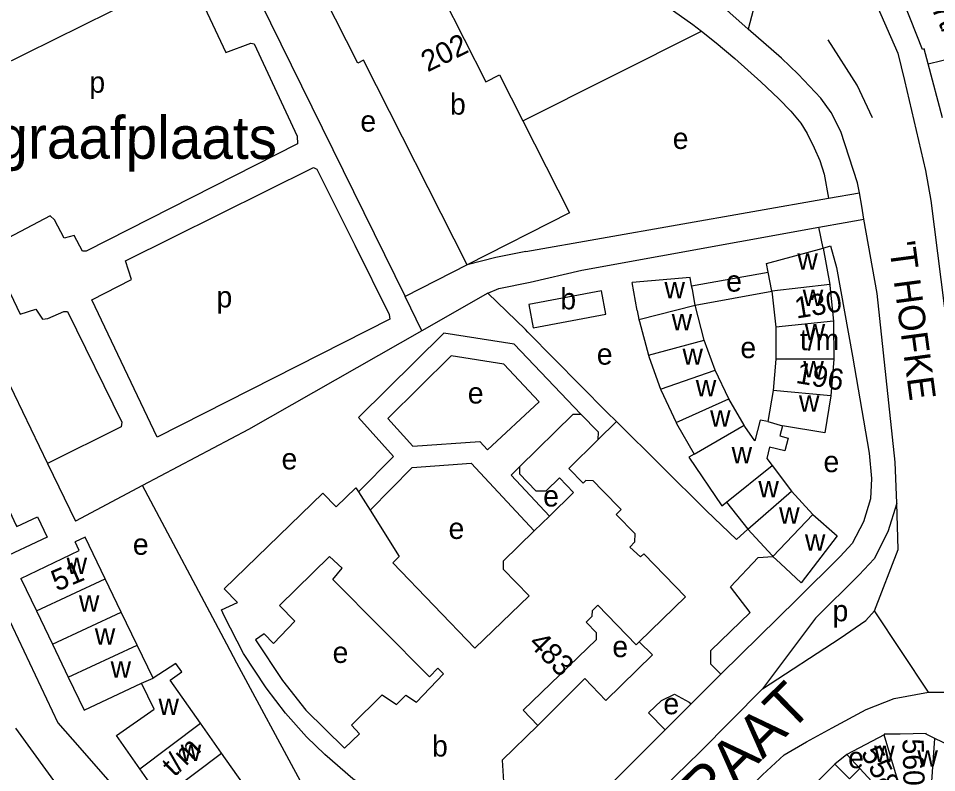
# Model space of a CAD drawing. Extents: x 162883 to 165538, y 383986 to 385172.
# Drawn here: x 163911.8 to 164085, y 384315.2 to 384457.6 of the extents above; entities that cross this region are included whole.
import ezdxf

# ---------------------------------------------------------------- set-up
doc = ezdxf.new("R2010")
doc.units = 0
for name, color, linetype in [('BLT_Basislijn', 7, 'Continuous'), ('BLT_Bebouwing', 7, 'Continuous'), ('BLT_Centroide', 7, 'Continuous'), ('BLT_Huisnummer', 7, 'Continuous'), ('BLT_Huisnummer_reeks', 7, 'Continuous'), ('BLT_Onderverdeling_panden', 7, 'Continuous'), ('BLT_Straatnaam', 7, 'Continuous'), ('BLT_Straatnaam_hoofdweg', 7, 'Continuous'), ('BLT_Terrein_beschrifting', 7, 'Continuous'), ('BLT_Vlakafsluiter', 7, 'Continuous')]:
    doc.layers.add(name, color=color, linetype=linetype)

msp = doc.modelspace()

# ---------------------------------------------------------------- linework, layer by layer
at = {"layer": 'BLT_Basislijn'}
for p, q in [((163886.33, 384437.63), (163943.9, 384466.17)), ((164006.95, 384438.24), (164040.63, 384455.16)), ((163886.33, 384437.63), (163917.29, 384373.57)), ((164063.81, 384428.18), (164064.64, 384423.62)), ((164007.5, 384413.59), (164064.64, 384423.62)), ((164064.64, 384423.62), (164070.44, 384424.64)), ((164063.59, 384414.21), (164062.79, 384418.14)), ((164067.77, 384419.04), (164071.31, 384419.66)), ((164038.8, 384407.07), (164053.23, 384409.69)), ((164039.45, 384403.47), (164053.95, 384406.1)), ((163987.9, 384398.58), (163984.73, 384405.1)), ((164000.34, 384405.72), (163987.9, 384398.58)), ((164007.43, 384398.86), (164000.34, 384405.72)), ((164010.06, 384385.2), (164000.31, 384376.13)), ((164021.13, 384378.04), (164024.6, 384381.5)), ((163975.93, 384368.19), (163982.54, 384374.91)), ((163917.29, 384373.57), (163922.54, 384362.69)), ((163978.13, 384364.73), (163986.08, 384372.81)), ((163935.22, 384369.4), (163922.54, 384362.69)), ((164058.65, 384347.89), (164044.46, 384333.93)), ((164044.46, 384333.93), (164038.7, 384328.19)), ((164038.7, 384328.19), (164033.81, 384323.31)), ((163924.02, 384306.15), (163911.31, 384323.59)), ((164033.81, 384323.31), (164013.39, 384302.89)), ((164068.09, 384318.64), (164065.79, 384316.81))]:
    msp.add_line(p, q, dxfattribs=at)
for points in [[(163952.32, 384470.24), (163955.43, 384464.7), (163984.73, 384405.1)], [(164049.47, 384455.56), (164039.63, 384464.36), (164031.94, 384470.28)], [(164025.61, 384468.33), (164028.5, 384463.91), (164039.03, 384456.44), (164040.63, 384455.16)], [(163943.9, 384466.17), (163950.95, 384451.13), (163955.61, 384452.91), (163956.25, 384452.75), (163964.39, 384435.33), (163964.46, 384433.9), (163924.56, 384413.66), (163923.89, 384413.66), (163922.33, 384416.58), (163920.39, 384416.11), (163918.58, 384419.58), (163917.78, 384420.28), (163906.37, 384414.35), (163907.09, 384412.19), (163912.15, 384401.77), (163915.08, 384402.72), (163916.35, 384400.81), (163917.32, 384400.94), (163920.33, 384402.27), (163921.06, 384402.24), (163931.28, 384381.36), (163931.15, 384380.49), (163917.29, 384373.57)], [(164073.79, 384459.86), (164077.68, 384451.03), (164078.94, 384445.85), (164082.94, 384428.86), (164083.91, 384423.22), (164088.33, 384388.44), (164089.21, 384364.99), (164089.69, 384360.4), (164090.61, 384357.27), (164091.09, 384356.07), (164094.4, 384348.23), (164098.89, 384337.66)], [(164040.63, 384455.16), (164043.44, 384452.94), (164046.96, 384450.01), (164051.83, 384445.61), (164055.24, 384442.39), (164057.52, 384440.07), (164059.37, 384437.82), (164060.6, 384435.83), (164061.92, 384433.16), (164062.96, 384430.78), (164063.81, 384428.18)], [(164070.44, 384424.64), (164070.11, 384426.53), (164066.97, 384436.23), (164065.11, 384439.84), (164063.17, 384442.49), (164058.89, 384447.05), (164055.76, 384450.09), (164049.47, 384455.56)], [(164072.92, 384438.82), (164070.02, 384444.95), (164064.55, 384453.5)], [(163975.24, 384414.76), (163981.73, 384401.7), (163981.87, 384400.78), (163937.99, 384378.54), (163925.61, 384404.46), (163933.1, 384408.32), (163932, 384411.79), (163967.45, 384429.41), (163968.08, 384429.1), (163975.24, 384414.76)], [(164070.88, 384422.15), (164070.44, 384424.64)], [(164000.34, 384405.72), (164002.41, 384406.62), (164008.36, 384407.8), (164018.1, 384410.06), (164062.79, 384418.14)], [(164062.79, 384418.14), (164067.77, 384419.04)], [(164077.48, 384366.07), (164077.2, 384373.82), (164073.78, 384405.64), (164071.31, 384419.66)], [(164063.59, 384414.21), (164064.98, 384414.66), (164066.1, 384410.58), (164069.15, 384393.83), (164072.28, 384375.52), (164072.7, 384370.74), (164072.51, 384366.92), (164071.19, 384362.53), (164069.08, 384358.46), (164066.83, 384356.04), (164058.65, 384347.89)], [(164007.5, 384413.59), (164001.84, 384412.47), (163996.47, 384411.07)], [(163996.47, 384411.07), (163984.73, 384405.1)], [(163987.9, 384398.58), (163955.2, 384379.98), (163935.22, 384369.4)], [(164017.89, 384382.87), (164005.31, 384396.07), (163992.04, 384398.14), (163975.97, 384382.23), (163982.54, 384374.91)], [(164024.6, 384381.5), (164022.82, 384383.27), (164007.92, 384398.37), (164007.43, 384398.86)], [(164010.06, 384385.2), (164003.34, 384392.33), (163993.42, 384393.87), (163981.49, 384382.07), (163986.19, 384376.83), (163998.81, 384377.73), (164000.31, 384376.13)], [(164049.39, 384361.14), (164047.29, 384359.24), (164041.59, 384364.6), (164024.6, 384381.5)], [(163986.08, 384372.81), (163997.19, 384373.61), (164009.09, 384360.84)], [(164006.32, 384372.96), (164004.73, 384371.39), (164011.96, 384363.64)], [(163953.02, 384335.9), (163951.11, 384339.44), (163935.22, 384369.4)], [(164077.48, 384366.07), (164075.84, 384360.64), (164073.21, 384355.55), (164070.42, 384352.56), (164062.18, 384344.35), (164052.17, 384331.03)], [(164073.3, 384345.74), (164077.79, 384357.34), (164077.48, 384366.07)], [(164044.24, 384333.88), (164042.44, 384335.66), (164042.39, 384338.27), (164049.82, 384345.45), (164046.13, 384350.3), (164051.37, 384355.84), (164054.11, 384356.04)], [(163907.39, 384349.55), (163919.21, 384324.59), (163921.98, 384321.44)], [(164052.17, 384331.03), (164066.83, 384340.61), (164071.69, 384343.92), (164073.3, 384345.74)], [(164028.92, 384339.93), (164031.4, 384337.42), (164022.62, 384328.85), (164018.64, 384333.01), (164009.77, 384324.1)], [(163994.61, 384284.11), (163966.15, 384312.12), (163965.02, 384313.63), (163953.02, 384335.9)], [(163964.42, 384228.4), (163986.24, 384250), (164052.16, 384314.79), (164056.26, 384318.57), (164060.48, 384321.02), (164065.34, 384323.67), (164071.72, 384327.14), (164076.99, 384329.2), (164083.5, 384330.4)], [(163996.88, 384276.8), (164040.36, 384319.07), (164052.17, 384331.03)], [(164033.81, 384323.31), (164030.64, 384326.48), (164033.12, 384328.86), (164035.59, 384330.04), (164038.35, 384328.5), (164038.7, 384328.19)], [(164083.5, 384330.4), (164088.02, 384330.42), (164090.13, 384329.25)], [(163921.98, 384321.44), (163926.89, 384315.85)], [(163926.89, 384315.85), (163930.34, 384311.93), (163974.78, 384266.34)]]:
    msp.add_lwpolyline(points, dxfattribs=at)
msp.add_lwpolyline([(163970.46, 384356.04), (163961.03, 384346.79), (163963.94, 384343.78), (163959.92, 384339.59), (163958.14, 384341.42), (163956.54, 384340.3), (163961.64, 384332.58), (163966, 384326.98), (163973.32, 384319.81), (163976.15, 384322.56), (163974.61, 384324.2), (163980.4, 384329.9), (163983.12, 384328.1), (163984.88, 384329.82), (163986.88, 384328.51), (163992.01, 384333.88), (163990.93, 384334.91), (163989.33, 384333.27), (163971.13, 384351.65), (163972.88, 384353.81)], close=True, dxfattribs=at)
at = {"layer": 'BLT_Bebouwing'}
for p, q in [((164086.13, 384438.81), (164083.42, 384448.97)), ((164063.59, 384414.21), (164064.86, 384407.33)), ((164053.95, 384406.1), (164053.23, 384409.69)), ((164028.54, 384402.47), (164027.58, 384407.71)), ((164038.93, 384406.38), (164038.8, 384407.07)), ((164039.45, 384403.47), (164038.93, 384406.38)), ((164053.95, 384406.1), (164054.67, 384399.27)), ((164028.54, 384402.47), (164028.86, 384400.74)), ((164041.18, 384396.82), (164039.45, 384403.47)), ((164054.67, 384399.27), (164054.69, 384393.25)), ((164043.25, 384391.19), (164041.18, 384396.82)), ((164054.69, 384393.25), (164054.18, 384387.35)), ((164065.63, 384393.28), (164065.07, 384386.31)), ((164045.81, 384385.77), (164043.25, 384391.19)), ((164054.18, 384387.35), (164053.2, 384381.46)), ((164048.71, 384380.78), (164045.81, 384385.77)), ((164052.97, 384374.53), (164053.96, 384373.21)), ((164053.96, 384373.21), (164057.61, 384368.32)), ((163975.46, 384368.94), (163975.93, 384368.19)), ((163975.93, 384368.19), (163978.13, 384364.73)), ((164057.61, 384368.32), (164061.69, 384363.91)), ((164045.36, 384366.27), (164049.39, 384361.14)), ((164011.96, 384363.64), (164009.09, 384360.84)), ((164075.09, 384322.34), (164068.09, 384318.64)), ((164090.11, 384319.01), (164084.65, 384321.68)), ((164003.04, 384317.58), (164003.33, 384313.56)), ((164065.79, 384316.81), (164061.48, 384312.49))]:
    msp.add_line(p, q, dxfattribs=at)
for points in [[(163985.08, 384481.37), (163994.35, 384463.08), (163991.78, 384461.77), (163999.96, 384445.61), (164002.53, 384446.95), (164006.95, 384438.24)], [(164083.42, 384448.97), (164082.65, 384451.82), (164082.35, 384451.7), (164077.72, 384463.52), (164084.2, 384468.61), (164083.4, 384470.22), (164095.51, 384476.23)], [(163996.47, 384411.07), (163976.92, 384449.67), (163975.84, 384449.13), (163963.12, 384474.23)], [(164006.95, 384438.24), (164015.76, 384420.85), (163996.47, 384411.07)], [(164053.23, 384409.69), (164052.92, 384411.29), (164063.59, 384414.21)], [(164038.8, 384407.07), (164038.51, 384408.7), (164027.58, 384407.71)], [(164021.81, 384406.15), (164008.09, 384403.6), (164008.92, 384399.17)], [(164008.92, 384399.17), (164022.64, 384401.72), (164021.81, 384406.15)], [(164064.86, 384407.33), (164064.89, 384407.15), (164065.54, 384400.42)], [(164028.86, 384400.74), (164028.93, 384400.37), (164030.65, 384393.99)], [(164065.54, 384400.42), (164065.55, 384400.31), (164065.63, 384393.28)], [(164030.65, 384393.99), (164030.76, 384393.57), (164032.95, 384387.59)], [(164032.95, 384387.59), (164033, 384387.46), (164035.86, 384381.27)], [(164065.07, 384386.31), (164063.92, 384379.33), (164055.93, 384380.7)], [(164006.32, 384372.96), (164016.44, 384382.89), (164017.89, 384382.87)], [(164017.89, 384382.87), (164021.15, 384379.55), (164021.13, 384378.04)], [(164053.2, 384381.46), (164051.7, 384381.71), (164050.7, 384377.81)], [(164035.86, 384381.27), (164035.93, 384381.13), (164039.27, 384375.31)], [(164050.7, 384377.81), (164048.83, 384380.57), (164048.71, 384380.78)], [(164055.93, 384380.7), (164055.45, 384378.77), (164056.98, 384378.37), (164056.39, 384375.95), (164053.5, 384376.63), (164052.97, 384374.53)], [(164028.1, 384358.75), (164028.12, 384360.29), (164024.53, 384363.96), (164025.48, 384364.9), (164021.99, 384368.47), (164020.19, 384370.31), (164018.81, 384370.33), (164018.36, 384369.88), (164015.66, 384372.64), (164021.13, 384378.04)], [(164039.27, 384375.31), (164038.28, 384374.75), (164044.48, 384365.56), (164045.36, 384366.27)], [(164006.32, 384372.96), (164006.31, 384371.63), (164009.43, 384368.42), (164011.36, 384368.4), (164013.85, 384370.86), (164016.53, 384368.11), (164011.96, 384363.64)], [(163950.11, 384345.96), (163953.13, 384347.34), (163950.62, 384349.92), (163969.2, 384367.98), (163971.75, 384365.36), (163975.46, 384368.94)], [(163908.97, 384367.04), (163911.33, 384361.98), (163911.49, 384361.65), (163915.42, 384363.49), (163917.2, 384359.67), (163907.8, 384355.28)], [(163978.13, 384364.73), (163983.65, 384356.02), (163982.4, 384354.81), (163997.91, 384338.7)], [(164061.69, 384363.91), (164066.25, 384359.91), (164059.49, 384351.03), (164055.54, 384354.71), (164054.11, 384356.04)], [(164049.39, 384361.14), (164053.97, 384356.17), (164054.11, 384356.04)], [(163928.17, 384351.81), (163924.4, 384359.67), (163922.49, 384358.79)], [(164009.09, 384360.84), (164003.23, 384355.12), (164003.21, 384353.63), (164008.12, 384348.61), (163997.91, 384338.7)], [(163912.25, 384351.87), (163923.27, 384357.16), (163922.49, 384358.79)], [(164029.17, 384355.92), (164027.12, 384357.8), (164028.1, 384358.75)], [(164028.92, 384339.93), (164037.65, 384348.39), (164029.78, 384356.51)], [(164029.78, 384356.51), (164029.17, 384355.92)], [(163912.25, 384351.87), (163915.18, 384345.76)], [(163931.2, 384345.5), (163928.17, 384351.81)], [(163915.18, 384345.76), (163918.21, 384339.45)], [(163934.18, 384339.3), (163931.2, 384345.5)], [(163978.64, 384311.36), (163978.02, 384311.77), (163976.46, 384312.92), (163974.9, 384314.06), (163969.6, 384318.62), (163966.17, 384321.96), (163962.15, 384326.43), (163958.5, 384331.21), (163954.27, 384337.68), (163950.62, 384344.8), (163950.11, 384345.96)], [(164006.99, 384326.99), (164020.85, 384340.33), (164020.86, 384341.61), (164018.92, 384343.61), (164020.06, 384344.72), (164020.07, 384345.81), (164021.09, 384346.8), (164028.33, 384339.35), (164028.92, 384339.93)], [(163918.21, 384339.45), (163921.19, 384333.25)], [(163937.19, 384333.03), (163934.18, 384339.3)], [(163946.14, 384324.55), (163940.43, 384332.69), (163942.61, 384334.22), (163941.48, 384335.83), (163937.19, 384333.03)], [(163921.19, 384333.25), (163924.19, 384326.99), (163935.02, 384332.11)], [(163934.7, 384315.92), (163930.28, 384322.2), (163937.37, 384327.19), (163935.02, 384332.11)], [(164006.99, 384326.99), (164009.77, 384324.1)], [(163950.1, 384318.92), (163946.14, 384324.55)], [(164009.77, 384324.1), (164003.04, 384317.58)], [(164078.15, 384322.5), (164075.11, 384322.45), (164075.09, 384322.34)], [(164084.65, 384321.68), (164083.04, 384322.47), (164083.04, 384322.59), (164078.15, 384322.5)], [(163954.05, 384313.29), (163950.1, 384318.92)], [(164068.09, 384318.64), (164070.56, 384315.97)], [(163938.66, 384310.29), (163934.7, 384315.92)], [(164070.56, 384315.97), (164068.61, 384314.02), (164065.79, 384316.81)]]:
    msp.add_lwpolyline(points, dxfattribs=at)
at = {"layer": 'BLT_Onderverdeling_panden'}
for p, q in [((164064.86, 384407.33), (164053.95, 384406.1)), ((164028.86, 384400.74), (164039.45, 384403.47)), ((164065.54, 384400.42), (164054.67, 384399.27)), ((164030.65, 384393.99), (164041.18, 384396.82)), ((164065.63, 384393.28), (164054.69, 384393.25)), ((164032.95, 384387.59), (164043.25, 384391.19)), ((164065.07, 384386.31), (164054.18, 384387.35)), ((164035.86, 384381.27), (164045.81, 384385.77)), ((164039.27, 384375.31), (164048.71, 384380.78)), ((164053.2, 384381.46), (164055.93, 384380.7)), ((164045.36, 384366.27), (164053.96, 384373.21)), ((164049.39, 384361.14), (164057.61, 384368.32)), ((164054.11, 384356.04), (164061.69, 384363.91)), ((163915.18, 384345.76), (163928.17, 384351.81)), ((163918.21, 384339.45), (163931.2, 384345.5)), ((163921.19, 384333.25), (163934.18, 384339.3)), ((163935.02, 384332.11), (163937.19, 384333.03)), ((163934.7, 384315.92), (163946.14, 384324.55)), ((164077.81, 384313.28), (164075.09, 384322.34)), ((164083.96, 384311.76), (164084.65, 384321.68)), ((163938.66, 384310.29), (163950.1, 384318.92)), ((164070.56, 384315.97), (164074.29, 384311.93))]:
    msp.add_line(p, q, dxfattribs=at)
msp.add_lwpolyline([(164083.42, 384448.97), (164088.57, 384450.26), (164095.19, 384452.14)], dxfattribs=at)
at = {"layer": 'BLT_Vlakafsluiter'}
for p, q in [((164053.09, 384469.63), (164049.47, 384455.56)), ((164071.31, 384419.66), (164070.88, 384422.15)), ((164083.5, 384330.4), (164073.3, 384345.74))]:
    msp.add_line(p, q, dxfattribs=at)

# ---------------------------------------------------------------- texts
at = {"layer": 'BLT_Centroide'}
for s, p in [('p', (163925.18, 384443.54)), ('b', (163993.22, 384439.41)), ('e', (163976.3, 384436.2)), ('e', (164035.23, 384432.93)), ('w', (164058.74, 384410.16)), ('w', (164033.67, 384404.72)), ('e', (164045.31, 384406)), ('p', (163949.16, 384403.02)), ('b', (164014.03, 384402.66)), ('w', (164059.76, 384403.28)), ('w', (164035.03, 384398.72)), ('w', (164060.13, 384396.84)), ('e', (164047.99, 384393.45)), ('e', (164020.91, 384392.22)), ('w', (164037.07, 384392.19)), ('w', (164059.87, 384389.81)), ('w', (164039.58, 384386.22)), ('e', (163996.57, 384384.88)), ('w', (164059.05, 384383.34)), ('w', (164042.28, 384380.53)), ('w', (164046.34, 384373.62)), ('e', (163961.43, 384372.45)), ('e', (164063.67, 384371.93)), ('w', (164051.39, 384367.19)), ('e', (164010.79, 384365.44)), ('w', (164055.3, 384362.19)), ('e', (163992.94, 384359.32)), ('e', (163933.38, 384356.33)), ('w', (164060.17, 384357.14)), ('w', (163920.88, 384352.72)), ('w', (163923.2, 384345.62)), ('p', (164065.38, 384343.78)), ('w', (163926.2, 384339.38)), ('e', (164023.84, 384337.02)), ('e', (163971.06, 384335.92)), ('w', (163929.18, 384333.16)), ('w', (163938.22, 384326.12)), ('e', (164033.47, 384326.23)), ('b', (163989.83, 384318.25)), ('w', (163942.41, 384317.41)), ('w', (164073.23, 384317.22)), ('w', (164081.39, 384316.33)), ('e', (164068.32, 384316.05))]:
    msp.add_text(s, height=4, dxfattribs=at).set_placement(p)
at = {"layer": 'BLT_Huisnummer'}
for s, rotation, p in [('202', 26.0935, (163989, 384447.37)), ('483', 314.3129, (164007.85, 384339.46)), ('560', 271.2507, (164078.58, 384321.61)), ('558', 297.3654, (164070.64, 384318.98))]:
    msp.add_text(s, height=4, rotation=rotation, dxfattribs=at).set_placement(p)
at = {"layer": 'BLT_Huisnummer_reeks'}
for s, rotation, p in [('117t/m127', 295.4373, (164081.38, 384464.89)), ('130', 9.4151, (164058.58, 384400.9)), ('t/m', 0.1728, (164059.22, 384394.94)), ('196', 350.2985, (164058.31, 384388.79)), ('51', 22.8033, (163919.04, 384349.36)), ('t/m', 44.0915, (163941.2, 384314.26))]:
    msp.add_text(s, height=4, rotation=rotation, dxfattribs=at).set_placement(p)
at = {"layer": 'BLT_Straatnaam'}
msp.add_text("'T HOFKE", height=5, rotation=277.6182, dxfattribs=at).set_placement((164075.96, 384415.23))
at = {"layer": 'BLT_Straatnaam_hoofdweg'}
msp.add_text('TONGELRESESTRAAT', height=8, rotation=44.3284, dxfattribs=at).set_placement((163979.48, 384246.63))
at = {"layer": 'BLT_Terrein_beschrifting'}
msp.add_text('Begraafplaats', height=8, rotation=359.8938, dxfattribs=at).set_placement((163894.55, 384431.16))

doc.saveas('drawing.dxf')
